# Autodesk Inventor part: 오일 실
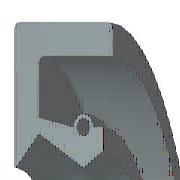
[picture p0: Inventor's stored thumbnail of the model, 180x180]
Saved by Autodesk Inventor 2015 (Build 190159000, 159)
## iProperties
IsCustomPart: 0
Created: 2014-10
Part Number: 오일 실
Material: 고무
Description: 오일-실
Document SubType Name: Modeling
Standard: KS B 2804
Designer: KYOUNG IL JANG
Standards Organization: KS
Language: ko-KR
Size Designation: D - 17 32 8
Categories: <MemberInstance><Categories><Category DisplayName="샤프트 부품" InternalName="7f7aeb1f-a693-4053-b835-cee3144e0d98" Mnemonic="SHFT"><Category DisplayName="실링" Intern
Density: 0.93 g/cm^3
Mass: 2.28027 g
Surface Area: 32.1224 cm^2
Volume: 2.45191 cm^3
Appearance: 고무 - 검은색 - 버전 1.1
Author: SeoGD™ [www.esajin.kr]
Revision Number: 1
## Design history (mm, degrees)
revolve "본체" stored, may be unused: angle "d17" = 90 deg
revolve "스프링1" stored, may be unused: angle "d18" = 90 deg
body "Solid1"
sketch "스케치1"
  geometry: L1 (0, 16)-(8, 16); L2 (8, 14.25)-(1.75, 14.25); L3 (1.75, 10.25)-(4.9, 8.5); L4 (4.9, 8.5)-(0, 8.5); L5 (0, 0)-(9.586, 0) reference; L6 (4.9, 8.5)-(6.3, 9.375); L7 (0, 18)-(0, -3) reference; L8 (-1.941, 0)-(11.507, 0) reference; L9 (4.2, 10.6)-(1.75, 11.21); L10 (1.75, 11.21)-(1.75, 14.25); L11 (0, 16)-(0, 8.588); L12 (4.9, 8.5)-(0, 8.5); L13 (1.75, 10.25)-(0.152, 8.528); L14 (8, 16)-(8, 14.25); L15 (5.6, 10.6)-(6.3, 10.6); L16 (6.3, 10.6)-(6.3, 9.375); C1 r 0.455 at (4.9, 10.6); A1 r 0.7 centre (4.9, 10.6) between (5.6, 10.6) and (4.2, 10.6); A2 r 0.088 centre (0.088, 8.588) between (0, 8.588) and (0.152, 8.528); 1 further point
  constraints: 28 end point, 5 horizontal alignment, 5 point on line, 4 point on circle, 4 vertical alignment, 3 centre point, 3 tangent, 2 collinear, 2 horizontal, 2 perpendicular, 1 coincident, 1 parallel
  dimensions: "d0" = 32 diameter of L1 L5 (= SD2); "d1" = 1.75 distance of L1.end L2.start (= SD); "d2" = 0.91 diameter of C1 (= SPDI); "d3" = 1.4 diameter of A1 (= SPDA); "d4" = 17 diameter of L3.end L5 (= NND); "d5" = 20.5 diameter of L3.start L5 (= TKDM); "d7" = 22.42 diameter of L9.end L5 (= TKDM + 0.24 x SWDT); "d8" = 1.75 distance between parallel lines of L11 L10 (= SD); "d9" = 4.9 distance from line of L11 C1.centre (= SPDST); "d10" = 21.2 diameter of C1.centre L5 (= HLDM); "d11" = 0.0875 radius of A2 (= 0.25 x LAB); "d12" = 6.3 distance between parallel lines of L11 L16 (= SDI); "d13" = 18.75 diameter of L6.end L5 (= ABDM); "d14" = 8 distance from line of L11 L1.end (= SWDT)
fillet "모깎기1" dims "d6" = 0.3 (= RR)
other parameters: "SD2" = 32 [user parameter; used in 1 equation term], "SWDT" = 8 [user parameter; used in 2 equation terms], "RR" = 0.3 [user parameter; used in 1 equation term], "SD" = 1.75 [user parameter; used in 2 equation terms], "NND" = 17 [user parameter; used in 1 equation term], "SPDA" = 1.4 [user parameter; used in 1 equation term], "SPDI" = 0.91 [user parameter; used in 1 equation term], "TKDM" = 20.5 [user parameter; used in 2 equation terms], "HLDM" = 21.2 [user parameter; used in 1 equation term], "ABDM" = 18.75 [user parameter; used in 1 equation term], "SDI" = 6.3 [user parameter; used in 1 equation term], "SPDST" = 4.9 [user parameter; used in 1 equation term], "LAB" = 0.35 [user parameter; used in 1 equation term], "d15" = 0, "d16" = 0, "d19" = 0
